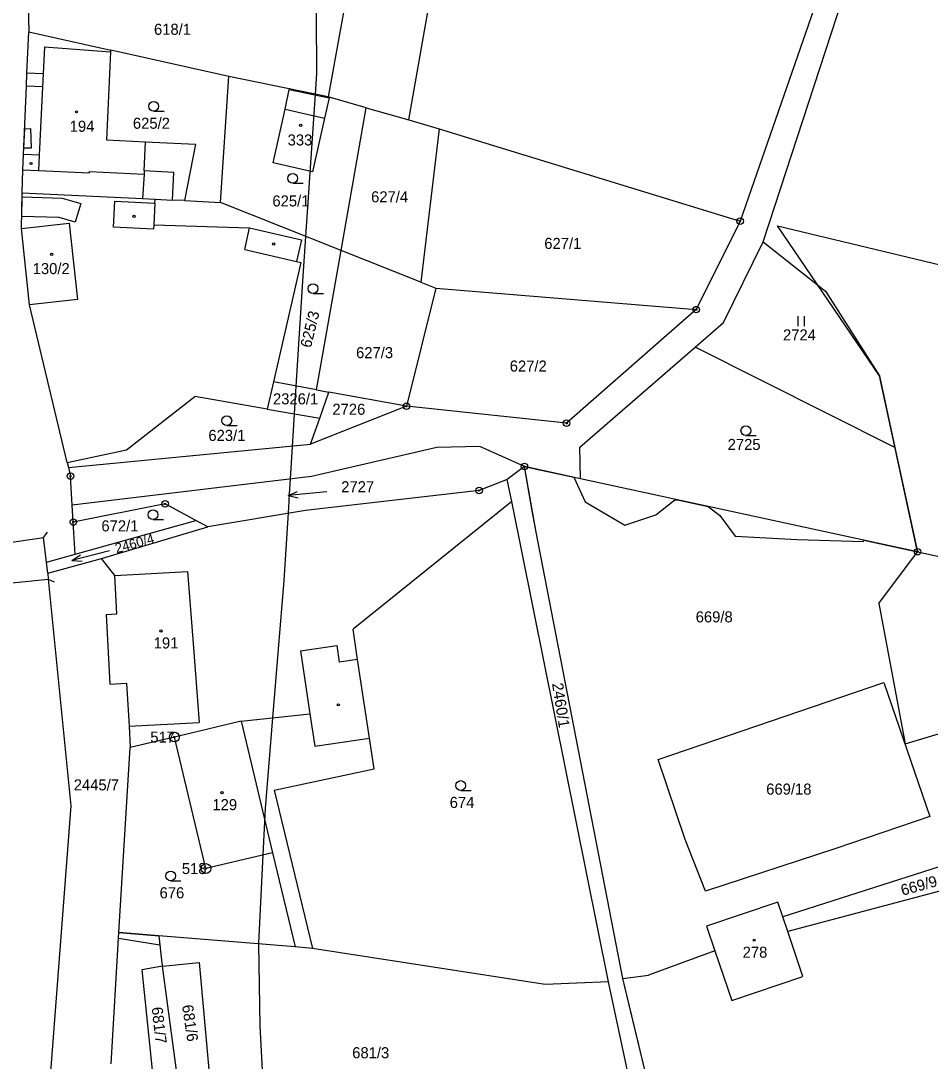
# Model space of a CAD drawing. Extents: x -546762 to -540209, y -1046851 to -1035694.
# Drawn here: x -542604.8 to -542465, y -1039628.5 to -1039468.6 of the extents above; entities that cross this region are included whole.
import ezdxf

# ---------------------------------------------------------------- set-up
doc = ezdxf.new("R2010")
doc.units = 0
for name, color, linetype in [('Vrstva 1', 7, 'Continuous'), ('Vrstva 17', 7, 'Continuous'), ('Vrstva 18', 7, 'Continuous'), ('Vrstva 19', 7, 'Continuous'), ('Vrstva 24', 7, 'Continuous'), ('Vrstva 25', 7, 'Continuous'), ('Vrstva 26', 7, 'Continuous'), ('Vrstva 3', 7, 'Continuous'), ('Vrstva 30', 7, 'Continuous'), ('Vrstva 37', 7, 'Continuous'), ('Vrstva 4', 7, 'Continuous'), ('Vrstva 52', 7, 'Continuous')]:
    doc.layers.add(name, color=color, linetype=linetype)

msp = doc.modelspace()

# ---------------------------------------------------------------- linework, layer by layer
at = {"layer": 'Vrstva 1'}
for p, q in [((-542564.21, -1039482.18), (-542563.55, -1039479.16)), ((-542563.55, -1039479.16), (-542557.43, -1039480.44)), ((-542557.43, -1039480.44), (-542558.13, -1039483.54)), ((-542566.03, -1039490.44), (-542564.21, -1039482.18)), ((-542558.13, -1039483.54), (-542560, -1039491.79)), ((-542540.52, -1039485.18), (-542494.25, -1039499.38)), ((-542560, -1039491.79), (-542566.03, -1039490.44)), ((-542541.02, -1039509.69), (-542501, -1039512.98)), ((-542559.36, -1039525.31), (-542557.47, -1039525.66)), ((-542566.93, -1039528.27), (-542558.87, -1039529.66)), ((-542597.7, -1039536.45), (-542597.5, -1039537.24)), ((-542596.45, -1039550.55), (-542577.91, -1039545.37)), ((-542596.45, -1039550.55), (-542596.75, -1039545.62)), ((-542592.42, -1039551.23), (-542576.06, -1039546.36)), ((-542506.85, -1039582.12), (-542472.17, -1039570.28)), ((-542472.17, -1039570.28), (-542465.1, -1039590.87)), ((-542502.69, -1039594.41), (-542506.85, -1039582.12)), ((-542465.1, -1039590.87), (-542479.55, -1039595.8)), ((-542499.59, -1039602.35), (-542502.69, -1039594.41)), ((-542479.55, -1039595.8), (-542499.59, -1039602.35))]:
    msp.add_line(p, q, dxfattribs=at)
for points in [[(-542604.44, -1039434.91), (-542603.61, -1039470.3)], [(-542550, -1039438.39), (-542557.58, -1039480.26)], [(-542545.2, -1039483.83), (-542537.82, -1039441.87)], [(-542479.99, -1039458.36), (-542494.25, -1039499.38)], [(-542490.7, -1039502.54), (-542476.73, -1039459.71)], [(-542603.87, -1039476.62), (-542603.61, -1039470.3)], [(-542603.61, -1039470.3), (-542591, -1039473.1)], [(-542591.01, -1039473.35), (-542591.67, -1039486.89)], [(-542591, -1039473.1), (-542591.01, -1039473.35)], [(-542572.86, -1039477.13), (-542591, -1039473.1)], [(-542603.95, -1039478.62), (-542603.87, -1039476.62)], [(-542574.12, -1039496.49), (-542572.86, -1039477.13)], [(-542557.58, -1039480.26), (-542572.86, -1039477.13)], [(-542604.39, -1039489.12), (-542603.95, -1039478.62)], [(-542551.73, -1039481.95), (-542557.58, -1039480.26)], [(-542555.59, -1039503.88), (-542551.73, -1039481.95)], [(-542551.73, -1039481.95), (-542545.2, -1039483.83)], [(-542545.2, -1039483.83), (-542540.52, -1039485.18)], [(-542540.52, -1039485.18), (-542543.34, -1039508.76)], [(-542591.67, -1039486.89), (-542585.63, -1039487.18)], [(-542585.63, -1039487.18), (-542577.98, -1039487.55)], [(-542577.98, -1039487.55), (-542579.68, -1039496.22)], [(-542604.5, -1039491.47), (-542604.39, -1039489.12)], [(-542604.59, -1039495.02), (-542604.5, -1039491.47)], [(-542604.73, -1039500.51), (-542604.59, -1039495.02)], [(-542604.59, -1039495.02), (-542586.1, -1039495.91)], [(-542586.1, -1039495.91), (-542584.18, -1039496)], [(-542584.2, -1039496.6), (-542584.18, -1039496)], [(-542584.18, -1039496), (-542581.51, -1039496.14)], [(-542584.2, -1039496.6), (-542584.37, -1039499.96)], [(-542579.68, -1039496.22), (-542581.51, -1039496.14)], [(-542579.68, -1039496.22), (-542574.12, -1039496.49)], [(-542555.59, -1039503.88), (-542574.12, -1039496.49)], [(-542603.46, -1039512.24), (-542604.73, -1039500.51)], [(-542584.37, -1039499.96), (-542569.68, -1039500.43)], [(-542569.68, -1039500.43), (-542561.69, -1039502.26)], [(-542494.25, -1039499.38), (-542501, -1039512.98)], [(-542561.69, -1039502.26), (-542562.45, -1039505.57)], [(-542559.36, -1039525.31), (-542555.59, -1039503.88)], [(-542543.34, -1039508.76), (-542555.59, -1039503.88)], [(-542496.83, -1039514.98), (-542490.7, -1039502.54)], [(-542490.7, -1039502.54), (-542481.15, -1039510.14)], [(-542562.45, -1039505.57), (-542561.76, -1039505.73)], [(-542561.76, -1039505.73), (-542565.97, -1039524.1)], [(-542543.34, -1039508.76), (-542541.02, -1039509.69)], [(-542541.02, -1039509.69), (-542545.54, -1039527.84)], [(-542481.15, -1039510.14), (-542472.85, -1039523.15)], [(-542597.7, -1039536.45), (-542603.46, -1039512.24)], [(-542501, -1039512.98), (-542520.94, -1039530.44)], [(-542501.17, -1039518.75), (-542496.83, -1039514.98)], [(-542518.89, -1039534.13), (-542501.17, -1039518.75)], [(-542470.46, -1039534.15), (-542501.17, -1039518.75)], [(-542472.85, -1039523.15), (-542470.46, -1039534.15)], [(-542565.97, -1039524.1), (-542566.93, -1039528.27)], [(-542559.36, -1039525.31), (-542565.97, -1039524.1)], [(-542588.6, -1039534.52), (-542578.08, -1039526.34)], [(-542566.93, -1039528.27), (-542578.08, -1039526.34)], [(-542558.87, -1039529.66), (-542557.47, -1039525.66)], [(-542545.54, -1039527.84), (-542557.47, -1039525.66)], [(-542545.54, -1039527.84), (-542560.27, -1039533.66)], [(-542520.94, -1039530.44), (-542545.54, -1039527.84)], [(-542560.27, -1039533.66), (-542558.87, -1039529.66)], [(-542597.5, -1039537.24), (-542560.27, -1039533.66)], [(-542540.88, -1039534.16), (-542560.16, -1039538.61)], [(-542534.25, -1039534.04), (-542540.88, -1039534.16)], [(-542527.42, -1039537.1), (-542534.25, -1039534.04)], [(-542518.77, -1039538.97), (-542518.89, -1039534.13)], [(-542470.46, -1039534.15), (-542466.98, -1039550.18)], [(-542597.7, -1039536.45), (-542588.6, -1039534.52)], [(-542597.5, -1039537.24), (-542597.18, -1039538.55)], [(-542527.42, -1039537.1), (-542530.05, -1039539.1)], [(-542525.62, -1039547.18), (-542527.42, -1039537.1)], [(-542518.77, -1039538.97), (-542527.42, -1039537.1)], [(-542596.91, -1039543.03), (-542597.18, -1039538.55)], [(-542560.16, -1039538.61), (-542596.91, -1039543.03)], [(-542530.05, -1039539.1), (-542534.38, -1039540.78)], [(-542529.37, -1039542.49), (-542530.05, -1039539.1)], [(-542466.98, -1039550.18), (-542518.77, -1039538.97)], [(-542534.38, -1039540.78), (-542561.06, -1039543.87)], [(-542596.75, -1039545.62), (-542596.91, -1039543.03)], [(-542582.64, -1039542.84), (-542596.75, -1039545.62)], [(-542577.91, -1039545.37), (-542582.64, -1039542.84)], [(-542561.06, -1039543.87), (-542576.06, -1039546.36)], [(-542529.37, -1039542.49), (-542553.75, -1039562.11)], [(-542514.51, -1039616.31), (-542529.37, -1039542.49)], [(-542576.06, -1039546.36), (-542577.91, -1039545.37)], [(-542512.31, -1039615.79), (-542525.62, -1039547.18)], [(-542610.81, -1039549.38), (-542601.31, -1039547.99)], [(-542600.87, -1039551.78), (-542601.31, -1039547.99)], [(-542472.96, -1039558.14), (-542466.98, -1039550.18)], [(-542466.98, -1039550.18), (-542459.63, -1039551.77)], [(-542600.87, -1039551.78), (-542596.45, -1039550.55)], [(-542600.68, -1039553.48), (-542592.42, -1039551.23)], [(-542590.38, -1039553.84), (-542592.42, -1039551.23)], [(-542600.68, -1039553.48), (-542600.59, -1039554.38)], [(-542610.29, -1039555.38), (-542600.59, -1039554.38)], [(-542600.59, -1039554.38), (-542597.11, -1039589.26)], [(-542590.06, -1039559.75), (-542590.38, -1039553.84)], [(-542472.96, -1039558.14), (-542468.89, -1039579.73)], [(-542591.71, -1039559.84), (-542590.06, -1039559.75)], [(-542591.71, -1039559.84), (-542591.14, -1039570.55)], [(-542553.05, -1039566.73), (-542553.75, -1039562.11)], [(-542551.23, -1039578.82), (-542553.05, -1039566.73)], [(-542591.14, -1039570.55), (-542588.55, -1039570.41)], [(-542588.55, -1039570.41), (-542588.19, -1039577.01)], [(-542570.96, -1039576.25), (-542560.38, -1039575.08)], [(-542560.38, -1039575.08), (-542559.63, -1039580.08)], [(-542588.19, -1039577.01), (-542588.02, -1039580.29)], [(-542570.96, -1039576.25), (-542581.22, -1039578.68)], [(-542581.22, -1039578.68), (-542588.02, -1039580.29)], [(-542576.37, -1039598.88), (-542581.22, -1039578.68)], [(-542559.63, -1039580.08), (-542551.23, -1039578.82)], [(-542550.52, -1039583.56), (-542551.23, -1039578.82)], [(-542468.89, -1039579.73), (-542462.77, -1039577.89)], [(-542589.74, -1039608.71), (-542588.02, -1039580.29)], [(-542565.88, -1039586.83), (-542550.52, -1039583.56)], [(-542565.88, -1039586.83), (-542559.98, -1039611.16)], [(-542597.11, -1039589.26), (-542602.29, -1039656.98)], [(-542450.87, -1039594.5), (-542487.7, -1039606.32)], [(-542566.11, -1039596.45), (-542576.37, -1039598.88)], [(-542566.11, -1039596.45), (-542562.63, -1039610.94)], [(-542448.16, -1039598.28), (-542486.94, -1039608.57)], [(-542488.48, -1039604.03), (-542499.45, -1039607.75)], [(-542487.7, -1039606.32), (-542488.48, -1039604.03)], [(-542486.94, -1039608.57), (-542487.7, -1039606.32)], [(-542499.45, -1039607.75), (-542498.15, -1039611.55)], [(-542590.94, -1039628.92), (-542589.74, -1039608.71)], [(-542583.63, -1039609.21), (-542589.74, -1039608.71)], [(-542562.63, -1039610.94), (-542583.63, -1039609.21)], [(-542583.63, -1039609.21), (-542583.15, -1039613.45)], [(-542484.6, -1039615.47), (-542486.94, -1039608.57)], [(-542559.98, -1039611.16), (-542562.63, -1039610.94)], [(-542524.23, -1039616.7), (-542559.98, -1039611.16)], [(-542498.15, -1039611.55), (-542508.34, -1039615.29)], [(-542498.15, -1039611.55), (-542495.56, -1039619.14)], [(-542583.04, -1039613.9), (-542586.21, -1039614.47)], [(-542583.15, -1039613.45), (-542583.04, -1039613.9)], [(-542583.04, -1039613.9), (-542577.39, -1039613.3)], [(-542580.66, -1039631.43), (-542583.04, -1039613.9)], [(-542577.39, -1039613.3), (-542575.81, -1039630.91)], [(-542586.21, -1039614.47), (-542584.43, -1039631.87)], [(-542512.31, -1039615.79), (-542508.34, -1039615.29)], [(-542499.07, -1039670.62), (-542512.31, -1039615.79)], [(-542495.56, -1039619.14), (-542484.6, -1039615.47)], [(-542514.51, -1039616.31), (-542524.23, -1039616.7)], [(-542509.76, -1039638.36), (-542514.51, -1039616.31)]]:
    msp.add_lwpolyline(points, dxfattribs=at)
at = {"layer": 'Vrstva 24'}
for centre, radius in [((-542494.25, -1039499.38), 0.5), ((-542494.25, -1039499.38), 0.1), ((-542501, -1039512.98), 0.5), ((-542501, -1039512.98), 0.1), ((-542545.54, -1039527.84), 0.5), ((-542545.54, -1039527.84), 0.1), ((-542520.94, -1039530.44), 0.5), ((-542520.94, -1039530.44), 0.1), ((-542527.42, -1039537.1), 0.5), ((-542527.42, -1039537.1), 0.1), ((-542597.18, -1039538.55), 0.5), ((-542597.18, -1039538.55), 0.1), ((-542534.38, -1039540.78), 0.5), ((-542534.38, -1039540.78), 0.1), ((-542582.64, -1039542.84), 0.5), ((-542582.64, -1039542.84), 0.1), ((-542596.75, -1039545.62), 0.5), ((-542596.75, -1039545.62), 0.1), ((-542466.98, -1039550.18), 0.5), ((-542466.98, -1039550.18), 0.1), ((-542581.22, -1039578.68), 0.75), ((-542581.22, -1039578.68), 0.1), ((-542576.37, -1039598.88), 0.75), ((-542576.37, -1039598.88), 0.1)]:
    msp.add_circle(centre, radius, dxfattribs=at)
at = {"layer": 'Vrstva 25'}
for p, q in [((-542584.39, -1039482.48), (-542582.79, -1039482.48)), ((-542563.02, -1039493.56), (-542561.42, -1039493.56)), ((-542559.91, -1039510.49), (-542558.31, -1039510.49)), ((-542485.36, -1039515.5), (-542485.36, -1039514)), ((-542484.36, -1039515.5), (-542484.36, -1039514)), ((-542573.16, -1039530.79), (-542571.56, -1039530.79)), ((-542493.38, -1039532.34), (-542491.78, -1039532.34)), ((-542584.5, -1039545.26), (-542582.9, -1039545.26)), ((-542537.21, -1039586.87), (-542535.61, -1039586.87)), ((-542581.8, -1039600.76), (-542580.2, -1039600.76))]:
    msp.add_line(p, q, dxfattribs=at)
for points in [[(-542563.75, -1039541.57), (-542562.3, -1039540.92)], [(-542557.77, -1039540.97), (-542563.75, -1039541.57), (-542562.2, -1039541.92)], [(-542591.17, -1039550.03), (-542596.99, -1039551.53), (-542595.41, -1039551.64)], [(-542596.99, -1039551.53), (-542595.66, -1039550.67)]]:
    msp.add_lwpolyline(points, dxfattribs=at)
for centre, radius in [((-542584.39, -1039481.73), 0.75), ((-542596.26, -1039482.58), 0.175), ((-542561.79, -1039484.67), 0.175), ((-542603.26, -1039490.52), 0.175), ((-542563.02, -1039492.81), 0.75), ((-542587.44, -1039498.65), 0.175), ((-542565.95, -1039502.91), 0.175), ((-542600.09, -1039504.48), 0.175), ((-542559.91, -1039509.74), 0.75), ((-542573.16, -1039530.04), 0.75), ((-542493.38, -1039531.59), 0.75), ((-542584.5, -1039544.51), 0.75), ((-542583.28, -1039562.36), 0.175), ((-542556.03, -1039573.72), 0.175), ((-542537.21, -1039586.12), 0.75), ((-542573.89, -1039587.21), 0.175), ((-542581.8, -1039600.01), 0.75), ((-542492.1, -1039609.89), 0.175)]:
    msp.add_circle(centre, radius, dxfattribs=at)
at = {"layer": 'Vrstva 26'}
for p, q in [((-542601.31, -1039547.99), (-542600.71, -1039547.19)), ((-542600.59, -1039554.38), (-542599.69, -1039554.81))]:
    msp.add_line(p, q, dxfattribs=at)
at = {"layer": 'Vrstva 3'}
for points in [[(-542601.19, -1039472.61), (-542601.39, -1039476.74)], [(-542601.19, -1039472.61), (-542591.01, -1039473.35)], [(-542591.01, -1039473.35), (-542591.67, -1039486.89)], [(-542601.39, -1039476.74), (-542601.49, -1039478.74)], [(-542601.49, -1039478.74), (-542601.99, -1039489.24)], [(-542566.03, -1039490.44), (-542564.21, -1039482.18)], [(-542564.21, -1039482.18), (-542558.13, -1039483.54)], [(-542558.13, -1039483.54), (-542560, -1039491.79)], [(-542591.67, -1039486.89), (-542585.63, -1039487.18)], [(-542585.85, -1039491.67), (-542585.63, -1039487.18)], [(-542601.99, -1039489.24), (-542602.11, -1039491.59)], [(-542560, -1039491.79), (-542566.03, -1039490.44)], [(-542602.11, -1039491.59), (-542594.26, -1039491.97)], [(-542594.26, -1039491.97), (-542594.25, -1039491.77)], [(-542594.25, -1039491.77), (-542585.88, -1039492.18)], [(-542585.85, -1039491.67), (-542585.88, -1039492.18)], [(-542604.73, -1039500.51), (-542597.37, -1039499.71)], [(-542603.46, -1039512.24), (-542604.73, -1039500.51)], [(-542597.37, -1039499.71), (-542596.1, -1039511.44)], [(-542596.1, -1039511.44), (-542603.46, -1039512.24)], [(-542590.38, -1039553.84), (-542579.21, -1039553.24)], [(-542579.21, -1039553.24), (-542578.35, -1039564.28)], [(-542590.06, -1039559.75), (-542590.38, -1039553.84)], [(-542591.71, -1039559.84), (-542590.06, -1039559.75)], [(-542591.71, -1039559.84), (-542591.14, -1039570.55)], [(-542578.35, -1039564.28), (-542577.41, -1039576.43)], [(-542591.14, -1039570.55), (-542588.55, -1039570.41)], [(-542588.55, -1039570.41), (-542588.19, -1039577.01)], [(-542588.19, -1039577.01), (-542577.41, -1039576.43)], [(-542570.96, -1039576.25), (-542581.22, -1039578.68)], [(-542570.96, -1039576.25), (-542566.11, -1039596.45)], [(-542576.37, -1039598.88), (-542581.22, -1039578.68)], [(-542566.11, -1039596.45), (-542576.37, -1039598.88)], [(-542488.48, -1039604.03), (-542499.45, -1039607.75)], [(-542487.7, -1039606.32), (-542488.48, -1039604.03)], [(-542486.94, -1039608.57), (-542487.7, -1039606.32)], [(-542499.45, -1039607.75), (-542498.15, -1039611.55)], [(-542484.6, -1039615.47), (-542486.94, -1039608.57)], [(-542498.15, -1039611.55), (-542495.56, -1039619.14)], [(-542495.56, -1039619.14), (-542484.6, -1039615.47)]]:
    msp.add_lwpolyline(points, dxfattribs=at)
at = {"layer": 'Vrstva 30'}
for p, q in [((-542589.79, -1039609.61), (-542589.74, -1039608.71)), ((-542589.74, -1039608.71), (-542583.63, -1039609.21)), ((-542583.63, -1039609.21), (-542583.46, -1039610.68)), ((-542583.46, -1039610.68), (-542589.79, -1039609.61))]:
    msp.add_line(p, q, dxfattribs=at)
for points in [[(-542603.35, -1039485.14), (-542603.25, -1039488.14), (-542604.35, -1039488.18), (-542604.22, -1039485.17), (-542603.35, -1039485.14)], [(-542598.44, -1039495.83), (-542595.6, -1039496.67), (-542596.46, -1039499.55), (-542598.92, -1039498.81), (-542604.68, -1039498.66), (-542604.61, -1039495.66), (-542598.44, -1039495.83)]]:
    msp.add_lwpolyline(points, dxfattribs=at)
at = {"layer": 'Vrstva 37'}
for centre in [(-542596.26, -1039482.58), (-542561.79, -1039484.67), (-542600.09, -1039504.48), (-542583.28, -1039562.36), (-542573.89, -1039587.21), (-542492.1, -1039609.89)]:
    msp.add_circle(centre, 0.175, dxfattribs=at)
at = {"layer": 'Vrstva 4'}
msp.add_line((-542564.21, -1039482.18), (-542558.13, -1039483.54), dxfattribs=at)
for points in [[(-542601.19, -1039472.61), (-542601.39, -1039476.74)], [(-542601.19, -1039472.61), (-542591.01, -1039473.35)], [(-542601.39, -1039476.74), (-542603.87, -1039476.62)], [(-542601.39, -1039476.74), (-542601.49, -1039478.74)], [(-542601.49, -1039478.74), (-542603.95, -1039478.62)], [(-542601.49, -1039478.74), (-542601.99, -1039489.24)], [(-542585.85, -1039491.67), (-542585.63, -1039487.18)], [(-542601.99, -1039489.24), (-542604.39, -1039489.12)], [(-542601.99, -1039489.24), (-542602.11, -1039491.59)], [(-542604.5, -1039491.47), (-542602.11, -1039491.59)], [(-542602.11, -1039491.59), (-542594.26, -1039491.97)], [(-542594.26, -1039491.97), (-542594.25, -1039491.77)], [(-542594.25, -1039491.77), (-542585.88, -1039492.18)], [(-542585.88, -1039492.18), (-542586.1, -1039495.91)], [(-542585.85, -1039491.67), (-542585.88, -1039492.18)], [(-542581.3, -1039491.89), (-542585.85, -1039491.67)], [(-542581.51, -1039496.14), (-542581.3, -1039491.89)], [(-542590.57, -1039500.3), (-542590.38, -1039496.31)], [(-542590.38, -1039496.31), (-542584.2, -1039496.6)], [(-542604.73, -1039500.51), (-542597.37, -1039499.71)], [(-542597.37, -1039499.71), (-542596.1, -1039511.44)], [(-542584.4, -1039500.6), (-542590.57, -1039500.3)], [(-542584.37, -1039499.96), (-542584.4, -1039500.6)], [(-542570.41, -1039503.75), (-542569.68, -1039500.43)], [(-542570.41, -1039503.75), (-542562.45, -1039505.57)], [(-542596.1, -1039511.44), (-542603.46, -1039512.24)], [(-542600.68, -1039553.48), (-542600.87, -1039551.78)], [(-542590.38, -1039553.84), (-542579.21, -1039553.24)], [(-542579.21, -1039553.24), (-542578.35, -1039564.28)], [(-542578.35, -1039564.28), (-542577.41, -1039576.43)], [(-542561.84, -1039565.43), (-542556.26, -1039564.59)], [(-542556.26, -1039564.59), (-542555.87, -1039567.15)], [(-542561.84, -1039565.43), (-542560.38, -1039575.08)], [(-542553.05, -1039566.73), (-542555.87, -1039567.15)], [(-542588.19, -1039577.01), (-542577.41, -1039576.43)], [(-542570.96, -1039576.25), (-542566.11, -1039596.45)]]:
    msp.add_lwpolyline(points, dxfattribs=at)
at = {"layer": 'Vrstva 52'}
for points in [[(-542563.85, -1039666.49), (-542565.05, -1039658.26), (-542565.68, -1039653.94), (-542566.63, -1039644.16), (-542567.25, -1039637.72), (-542568.04, -1039623.08), (-542568.26, -1039610.48), (-542568.26, -1039610.33), (-542567.58, -1039596.8), (-542567.22, -1039589.66), (-542566.07, -1039575.71), (-542564.34, -1039554.62), (-542563.64, -1039543.41), (-542563.51, -1039541.35), (-542563.21, -1039536.56), (-542562.74, -1039528.99), (-542562.48, -1039524.74), (-542561.47, -1039508.59), (-542561.01, -1039501.72), (-542559.54, -1039479.86), (-542559.32, -1039476.62), (-542559.51, -1039441.98)], [(-542499.07, -1039670.62), (-542511.07, -1039620.92), (-542512.31, -1039615.79), (-542525.62, -1039547.18), (-542526.21, -1039543.88), (-542527.42, -1039537.1), (-542524.83, -1039537.67), (-542519.83, -1039538.75), (-542518.1, -1039542.5), (-542512, -1039546.1), (-542507.2, -1039544.5), (-542504.3, -1039542.2), (-542503.88, -1039542.2), (-542499.19, -1039543.22), (-542497.4, -1039544.6), (-542495, -1039547.8), (-542485.5, -1039548.3), (-542475.3, -1039548.6), (-542475.27, -1039548.39), (-542466.98, -1039550.18), (-542470.54, -1039533.8), (-542472.85, -1039523.15), (-542488.53, -1039500.1), (-542444.7, -1039510.58)]]:
    msp.add_lwpolyline(points, dxfattribs=at)

# ---------------------------------------------------------------- texts
at = {"layer": 'Vrstva 17'}
for s, p in [('517', (-542584.92, -1039579.53)), ('518', (-542580.07, -1039599.73))]:
    msp.add_text(s, height=1.7, dxfattribs=at).set_placement(p)
at = {"layer": 'Vrstva 18'}
for s, p in [('618/1', (-542584.35, -1039470.74)), ('625/2', (-542587.59, -1039485.18)), ('625/1', (-542566.15, -1039497.12)), ('627/4', (-542550.98, -1039496.49)), ('627/1', (-542524.36, -1039503.65)), ('2724', (-542487.67, -1039517.71)), ('627/3', (-542553.29, -1039520.44)), ('627/2', (-542529.67, -1039522.5)), ('2326/1', (-542566.06, -1039527.54)), ('2726', (-542556.93, -1039529.14)), ('623/1', (-542575.99, -1039533.16)), ('2725', (-542496.18, -1039534.55)), ('2727', (-542555.57, -1039541.05)), ('672/1', (-542592.43, -1039547.06)), ('669/8', (-542501.09, -1039561.05)), ('2445/7', (-542596.68, -1039586.87)), ('669/18', (-542490.25, -1039587.52)), ('674', (-542538.9, -1039589.57)), ('676', (-542583.49, -1039603.46)), ('681/3', (-542553.88, -1039628.04))]:
    msp.add_text(s, height=1.7, dxfattribs=at).set_placement(p)
for s, height, rotation, p in [('625/3', 1.7, 76.2081, (-542560.24, -1039518.95)), ('2460/4', 1.5, 15.3, (-542590.1, -1039550.44)), ('2460/1', 1.7, 279, (-542523.18, -1039570.47)), ('669/9', 1.7, 15.4134, (-542469.3, -1039603.08)), ('681/7', 1.7, 276.728, (-542584.73, -1039620.25)), ('681/6', 1.7, 278.5038, (-542580.05, -1039619.94))]:
    msp.add_text(s, height=height, rotation=rotation, dxfattribs=at).set_placement(p)
at = {"layer": 'Vrstva 19'}
for s, p in [('194', (-542597.3, -1039485.64)), ('333', (-542563.81, -1039487.75)), ('130/2', (-542602.99, -1039507.52)), ('191', (-542584.39, -1039565.06)), ('129', (-542575.37, -1039589.91)), ('278', (-542493.87, -1039612.59))]:
    msp.add_text(s, height=1.7, dxfattribs=at).set_placement(p)

doc.saveas('drawing.dxf')
